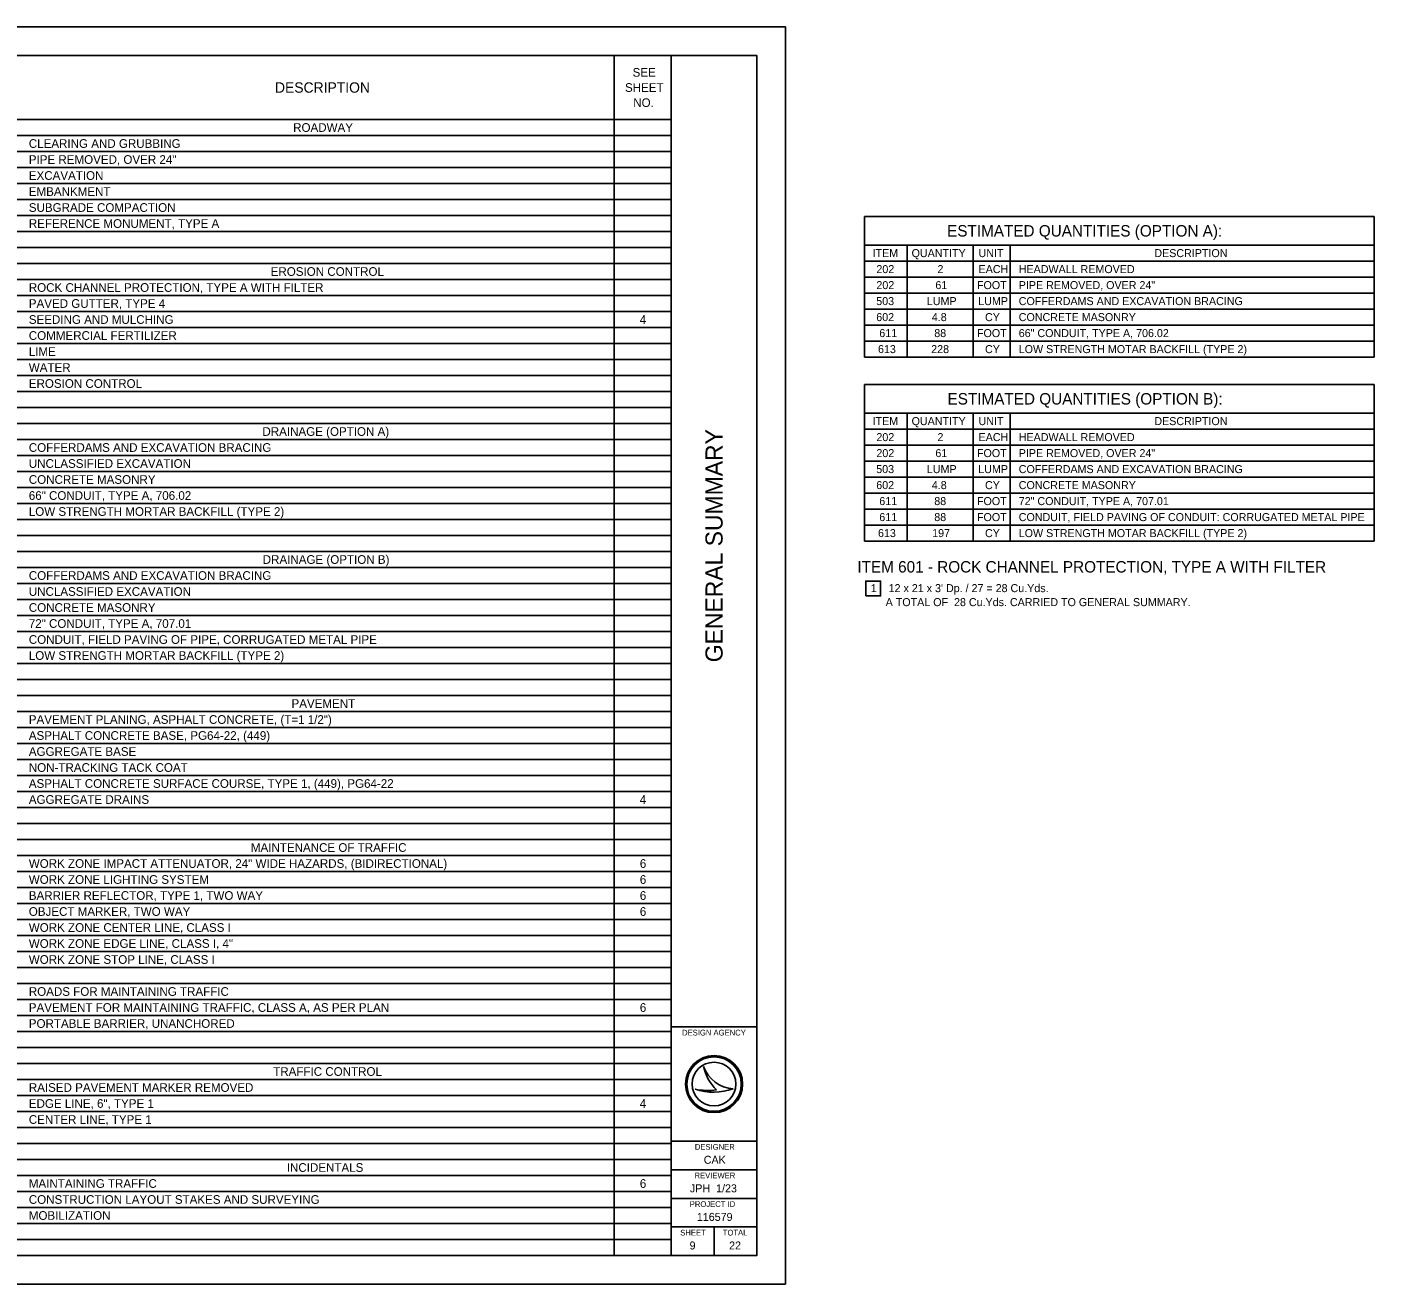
# Model space of a CAD drawing. Extents: x 0 to 44.3, y 0 to 22.
# Drawn here: x 20.73 to 44.3, y 0 to 22 of the extents above; entities that cross this region are included whole.
import ezdxf

# ---------------------------------------------------------------- set-up
doc = ezdxf.new("R2010")
doc.units = 0
for name, color, linetype in [('SH_Border', 7, 'Continuous'), ('SH_Cut_Line', 7, 'Continuous'), ('SH_Data', 7, 'Continuous'), ('SH_Text', 7, 'Continuous')]:
    doc.layers.add(name, color=color, linetype=linetype)

msp = doc.modelspace()

# ---------------------------------------------------------------- linework, layer by layer
at = {"layer": 'SH_Border'}
for p, q in [((32, 0.5), (32, 21.5)), ((32, 4.5), (33.5, 4.5)), ((32, 2.5), (33.5, 2.5)), ((32, 2), (33.5, 2)), ((32, 1.5), (33.5, 1.5)), ((32, 1), (33.5, 1))]:
    msp.add_line(p, q, dxfattribs=at)
msp.add_lwpolyline([(1.5, 21.5), (33.5, 21.5), (33.5, 0.5), (1.5, 0.5)], close=True, dxfattribs=at)
at = {"layer": 'SH_Cut_Line'}
msp.add_lwpolyline([(0, 0), (34, 0), (34, 22), (0, 22)], close=True, dxfattribs=at)
at = {"layer": 'SH_Data'}
for p, q in [((35.382, 18.682), (44.3, 18.682)), ((35.382, 16.222), (35.382, 18.682)), ((44.3, 18.682), (44.3, 16.222)), ((44.3, 18.182), (35.382, 18.182)), ((36.132, 16.222), (36.132, 18.182)), ((37.282, 16.222), (37.282, 18.182)), ((37.932, 16.222), (37.932, 18.182)), ((35.757, 18.042), (35.757, 18.042)), ((36.707, 18.042), (36.707, 18.042)), ((37.607, 18.042), (37.607, 18.042)), ((41.116, 18.042), (41.116, 18.042)), ((44.3, 17.902), (35.382, 17.902)), ((35.757, 17.762), (35.757, 17.762)), ((36.707, 17.762), (36.707, 17.762)), ((37.607, 17.762), (37.607, 17.762)), ((38.082, 17.762), (38.082, 17.762)), ((44.3, 17.622), (35.382, 17.622)), ((35.757, 17.482), (35.757, 17.482)), ((36.707, 17.482), (36.707, 17.482)), ((37.607, 17.482), (37.607, 17.482)), ((38.082, 17.482), (38.082, 17.482)), ((44.3, 17.342), (35.382, 17.342)), ((44.3, 17.062), (35.382, 17.062)), ((35.757, 17.202), (35.757, 17.202)), ((36.707, 17.202), (36.707, 17.202)), ((37.607, 17.202), (37.607, 17.202)), ((38.082, 17.202), (38.082, 17.202)), ((44.3, 16.782), (35.382, 16.782)), ((35.757, 16.922), (35.757, 16.922)), ((36.707, 16.922), (36.707, 16.922)), ((37.607, 16.922), (37.607, 16.922)), ((38.082, 16.922), (38.082, 16.922)), ((44.3, 16.502), (35.382, 16.502)), ((35.757, 16.642), (35.757, 16.642)), ((36.707, 16.642), (36.707, 16.642)), ((37.607, 16.642), (37.607, 16.642)), ((38.082, 16.642), (38.082, 16.642)), ((35.757, 16.362), (35.757, 16.362)), ((36.707, 16.362), (36.707, 16.362)), ((37.607, 16.362), (37.607, 16.362)), ((38.082, 16.362), (38.082, 16.362)), ((44.3, 16.222), (35.382, 16.222)), ((35.382, 15.742), (44.3, 15.742)), ((35.382, 13.002), (35.382, 15.742)), ((44.3, 15.742), (44.3, 13.002)), ((44.3, 15.242), (35.382, 15.242)), ((35.757, 15.102), (35.757, 15.102)), ((36.132, 13.002), (36.132, 15.242)), ((36.707, 15.102), (36.707, 15.102)), ((37.282, 13.002), (37.282, 15.242)), ((37.607, 15.102), (37.607, 15.102)), ((37.932, 13.002), (37.932, 15.242)), ((41.116, 15.102), (41.116, 15.102)), ((44.3, 14.962), (35.382, 14.962)), ((44.3, 14.682), (35.382, 14.682)), ((35.757, 14.822), (35.757, 14.822)), ((36.707, 14.822), (36.707, 14.822)), ((37.607, 14.822), (37.607, 14.822)), ((38.082, 14.822), (38.082, 14.822)), ((44.3, 14.402), (35.382, 14.402)), ((35.757, 14.542), (35.757, 14.542)), ((36.707, 14.542), (36.707, 14.542)), ((37.607, 14.542), (37.607, 14.542)), ((38.082, 14.542), (38.082, 14.542)), ((35.757, 14.262), (35.757, 14.262)), ((36.707, 14.262), (36.707, 14.262)), ((37.607, 14.262), (37.607, 14.262)), ((38.082, 14.262), (38.082, 14.262)), ((44.3, 14.122), (35.382, 14.122)), ((35.757, 13.982), (35.757, 13.982)), ((36.707, 13.982), (36.707, 13.982)), ((37.607, 13.982), (37.607, 13.982)), ((38.082, 13.982), (38.082, 13.982)), ((44.3, 13.842), (35.382, 13.842)), ((35.757, 13.702), (35.757, 13.702)), ((36.707, 13.702), (36.707, 13.702)), ((37.607, 13.702), (37.607, 13.702)), ((38.082, 13.702), (38.082, 13.702)), ((44.3, 13.562), (35.382, 13.562)), ((44.3, 13.282), (35.382, 13.282)), ((35.757, 13.422), (35.757, 13.422)), ((36.707, 13.422), (36.707, 13.422)), ((37.607, 13.422), (37.607, 13.422)), ((38.082, 13.422), (38.082, 13.422)), ((44.3, 13.002), (35.382, 13.002)), ((35.757, 13.142), (35.757, 13.142)), ((36.707, 13.142), (36.707, 13.142)), ((37.607, 13.142), (37.607, 13.142)), ((38.082, 13.142), (38.082, 13.142)), ((32.567, 3.81), (32.567, 3.81)), ((32.417, 3.41), (32.417, 3.41)), ((32.75, 3.5), (32.75, 3.5)), ((33.087, 3.419), (33.087, 3.419)), ((32.75, 0.5), (32.75, 1)), ((32.375, 0.675), (32.375, 0.675))]:
    msp.add_line(p, q, dxfattribs=at)
msp.add_lwpolyline([(35.405, 12.043), (35.665, 12.043), (35.665, 12.303), (35.405, 12.303)], close=True, dxfattribs=at)
for radius in [0.5, 0.477, 0.477, 0.382]:
    msp.add_circle((32.75, 3.5), radius, dxfattribs=at)
for centre, radius, start, end in [((33.116, 3.998), 0.58, 198.9257, 198.9319), ((33.347, 3.97), 0.796, 191.6379, 191.6421), ((33.116, 3.998), 0.58, 198.9319, 267.1657), ((33.347, 3.97), 0.796, 191.6421, 226.0947), ((32.739, 4.37), 1.013, 251.4576, 290.0832), ((32.648, 4.654), 1.266, 259.4964, 259.4995), ((32.739, 4.37), 1.013, 251.4527, 251.4576), ((32.648, 4.654), 1.266, 259.4995, 276.6672)]:
    msp.add_arc(centre, radius, start, end, dxfattribs=at)
at = {"layer": 'SH_Text'}
for p, q in [((1.5, 21.5), (32, 21.5)), ((31.002, 21.5), (31.002, 0.5)), ((32, 21.5), (32, 0.5)), ((1.5, 20.38), (32, 20.38)), ((1.5, 20.1), (32, 20.1)), ((1.5, 19.82), (32, 19.82)), ((1.5, 19.54), (32, 19.54)), ((1.5, 19.26), (32, 19.26)), ((1.5, 18.98), (32, 18.98)), ((1.5, 18.7), (32, 18.7)), ((1.5, 18.42), (32, 18.42)), ((1.5, 18.14), (32, 18.14)), ((1.5, 17.86), (32, 17.86)), ((1.5, 17.58), (32, 17.58)), ((1.5, 17.3), (32, 17.3)), ((1.5, 17.02), (32, 17.02)), ((1.5, 16.74), (32, 16.74)), ((1.5, 16.46), (32, 16.46)), ((1.5, 16.18), (32, 16.18)), ((1.5, 15.9), (32, 15.9)), ((1.5, 15.62), (32, 15.62)), ((1.5, 15.34), (32, 15.34)), ((1.5, 15.06), (32, 15.06)), ((1.5, 14.78), (32, 14.78)), ((1.5, 14.5), (32, 14.5)), ((1.5, 14.22), (32, 14.22)), ((1.5, 13.94), (32, 13.94)), ((1.5, 13.66), (32, 13.66)), ((1.5, 13.38), (32, 13.38)), ((1.5, 13.1), (32, 13.1)), ((1.5, 12.82), (32, 12.82)), ((1.5, 12.54), (32, 12.54)), ((1.5, 12.26), (32, 12.26)), ((1.5, 11.98), (32, 11.98)), ((1.5, 11.7), (32, 11.7)), ((1.5, 11.42), (32, 11.42)), ((1.5, 11.14), (32, 11.14)), ((1.5, 10.86), (32, 10.86)), ((1.5, 10.58), (32, 10.58)), ((1.5, 10.3), (32, 10.3)), ((1.5, 10.02), (32, 10.02)), ((1.5, 9.74), (32, 9.74)), ((1.5, 9.46), (32, 9.46)), ((1.5, 9.18), (32, 9.18)), ((1.5, 8.9), (32, 8.9)), ((1.5, 8.62), (32, 8.62)), ((1.5, 8.34), (32, 8.34)), ((1.5, 8.06), (32, 8.06)), ((1.5, 7.78), (32, 7.78)), ((1.5, 7.5), (32, 7.5)), ((1.5, 7.22), (32, 7.22)), ((1.5, 6.94), (32, 6.94)), ((1.5, 6.66), (32, 6.66)), ((1.5, 6.38), (32, 6.38)), ((1.5, 6.1), (32, 6.1)), ((1.5, 5.82), (32, 5.82)), ((1.5, 5.54), (32, 5.54)), ((1.5, 5.26), (32, 5.26)), ((1.5, 4.98), (32, 4.98)), ((1.5, 4.7), (32, 4.7)), ((1.5, 4.42), (32, 4.42)), ((1.5, 4.14), (32, 4.14)), ((1.5, 3.86), (32, 3.86)), ((1.5, 3.58), (32, 3.58)), ((1.5, 3.3), (32, 3.3)), ((1.5, 3.02), (32, 3.02)), ((1.5, 2.74), (32, 2.74)), ((1.5, 2.46), (32, 2.46)), ((1.5, 2.18), (32, 2.18)), ((1.5, 1.9), (32, 1.9)), ((1.5, 1.62), (32, 1.62)), ((1.5, 1.34), (32, 1.34)), ((1.5, 1.06), (32, 1.06)), ((1.5, 0.78), (32, 0.78)), ((1.5, 0.5), (32, 0.5))]:
    msp.add_line(p, q, dxfattribs=at)

# ---------------------------------------------------------------- texts
at = {"layer": 'SH_Data'}
for s, height, p in [('ESTIMATED QUANTITIES (OPTION A):', 0.2, (36.828, 18.332)), ('ITEM', 0.14, (35.524, 17.972)), ('QUANTITY', 0.14, (36.207, 17.972)), ('UNIT', 0.14, (37.379, 17.972)), ('DESCRIPTION', 0.14, (40.455, 17.972)), ('202', 0.14, (35.591, 17.692)), ('2', 0.14, (36.659, 17.692)), ('EACH', 0.14, (37.379, 17.692)), ('HEADWALL REMOVED', 0.14, (38.082, 17.692)), ('202', 0.14, (35.591, 17.412)), ('61', 0.14, (36.623, 17.412)), ('FOOT', 0.14, (37.351, 17.412)), ('PIPE REMOVED, OVER 24"', 0.14, (38.082, 17.412)), ('503', 0.14, (35.588, 17.132)), ('LUMP', 0.14, (36.474, 17.132)), ('LUMP', 0.14, (37.374, 17.132)), ('COFFERDAMS AND EXCAVATION BRACING', 0.14, (38.082, 17.132)), ('602', 0.14, (35.589, 16.852)), ('4.8', 0.14, (36.561, 16.852)), ('CY', 0.14, (37.492, 16.852)), ('CONCRETE MASONRY', 0.14, (38.082, 16.852)), ('611', 0.14, (35.642, 16.572)), ('88', 0.14, (36.604, 16.572)), ('FOOT', 0.14, (37.351, 16.572)), ('66" CONDUIT, TYPE A, 706.02', 0.14, (38.082, 16.572)), ('613', 0.14, (35.619, 16.292)), ('228', 0.14, (36.55, 16.292)), ('CY', 0.14, (37.492, 16.292)), ('LOW STRENGTH MOTAR BACKFILL (TYPE 2)', 0.14, (38.082, 16.292)), ('ESTIMATED QUANTITIES (OPTION B):', 0.2, (36.836, 15.392)), ('ITEM', 0.14, (35.524, 15.032)), ('QUANTITY', 0.14, (36.207, 15.032)), ('UNIT', 0.14, (37.379, 15.032)), ('DESCRIPTION', 0.14, (40.455, 15.032)), ('202', 0.14, (35.591, 14.752)), ('2', 0.14, (36.659, 14.752)), ('EACH', 0.14, (37.379, 14.752)), ('HEADWALL REMOVED', 0.14, (38.082, 14.752)), ('202', 0.14, (35.591, 14.472)), ('61', 0.14, (36.623, 14.472)), ('FOOT', 0.14, (37.351, 14.472)), ('PIPE REMOVED, OVER 24"', 0.14, (38.082, 14.472)), ('503', 0.14, (35.588, 14.192)), ('LUMP', 0.14, (36.474, 14.192)), ('LUMP', 0.14, (37.374, 14.192)), ('COFFERDAMS AND EXCAVATION BRACING', 0.14, (38.082, 14.192)), ('602', 0.14, (35.589, 13.912)), ('4.8', 0.14, (36.561, 13.912)), ('CY', 0.14, (37.492, 13.912)), ('CONCRETE MASONRY', 0.14, (38.082, 13.912)), ('611', 0.14, (35.642, 13.632)), ('88', 0.14, (36.604, 13.632)), ('FOOT', 0.14, (37.351, 13.632)), ('72" CONDUIT, TYPE A, 707.01', 0.14, (38.082, 13.632)), ('611', 0.14, (35.642, 13.352)), ('88', 0.14, (36.604, 13.352)), ('FOOT', 0.14, (37.351, 13.352)), ('CONDUIT, FIELD PAVING OF CONDUIT: CORRUGATED METAL PIPE', 0.14, (38.082, 13.352)), ('613', 0.14, (35.619, 13.072)), ('197', 0.14, (36.567, 13.072)), ('CY', 0.14, (37.492, 13.072)), ('LOW STRENGTH MOTAR BACKFILL (TYPE 2)', 0.14, (38.082, 13.072)), ('ITEM 601 - ROCK CHANNEL PROTECTION, TYPE A WITH FILTER', 0.2, (35.258, 12.452)), ("1    12 x 21 x 3' Dp. / 27 = 28 Cu.Yds.", 0.14, (35.493, 12.109)), ('     A TOTAL OF  28 Cu.Yds. CARRIED TO GENERAL SUMMARY. ', 0.14, (35.493, 11.864)), ('DESIGN AGENCY', 0.1, (32.191, 4.35)), ('DESIGNER', 0.1, (32.414, 2.35)), ('CAK', 0.14, (32.57, 2.105)), ('REVIEWER', 0.1, (32.409, 1.85)), ('JPH  1/23', 0.14, (32.328, 1.605)), ('PROJECT ID', 0.1, (32.325, 1.35)), ('116579', 0.14, (32.449, 1.105)), ('SHEET', 0.1, (32.158, 0.85)), ('TOTAL', 0.1, (32.903, 0.85)), ('9', 0.14, (32.322, 0.605)), ('22', 0.14, (33.013, 0.605))]:
    msp.add_text(s, height=height, dxfattribs=at).set_placement(p)
msp.add_text('GENERAL SUMMARY', height=0.3, rotation=90, dxfattribs=at).set_placement((32.9, 10.882))
at = {"layer": 'SH_Text'}
for s, height, p in [('SEE ', 0.1515, (31.325, 21.129)), ('DESCRIPTION', 0.18184, (25.067, 20.849)), ('SHEET ', 0.1515, (31.192, 20.864)), ('NO.', 0.1515, (31.336, 20.599)), ('ROADWAY', 0.1515, (25.385, 20.164)), ('CLEARING AND GRUBBING', 0.15153, (20.759, 19.884)), ('PIPE REMOVED, OVER 24"', 0.15153, (20.759, 19.604)), ('EXCAVATION', 0.1515, (20.759, 19.324)), ('EMBANKMENT', 0.1515, (20.759, 19.044)), ('SUBGRADE COMPACTION', 0.15153, (20.759, 18.764)), ('REFERENCE MONUMENT, TYPE A', 0.15153, (20.759, 18.484)), ('EROSION CONTROL', 0.15153, (24.992, 17.644)), ('ROCK CHANNEL PROTECTION, TYPE A WITH FILTER', 0.15153, (20.759, 17.364)), ('PAVED GUTTER, TYPE 4', 0.15153, (20.759, 17.084)), ('SEEDING AND MULCHING', 0.15153, (20.759, 16.804)), ('4', 0.152, (31.45, 16.804)), ('COMMERCIAL FERTILIZER', 0.15153, (20.759, 16.524)), ('LIME', 0.1515, (20.759, 16.244)), ('WATER', 0.1515, (20.759, 15.964)), ('EROSION CONTROL', 0.15153, (20.759, 15.684)), ('DRAINAGE (OPTION A)', 0.15153, (24.847, 14.844)), ('COFFERDAMS AND EXCAVATION BRACING', 0.15153, (20.759, 14.564)), ('UNCLASSIFIED EXCAVATION', 0.15153, (20.759, 14.284)), ('CONCRETE MASONRY', 0.15153, (20.759, 14.004)), ('66" CONDUIT, TYPE A, 706.02', 0.15153, (20.759, 13.724)), ('LOW STRENGTH MORTAR BACKFILL (TYPE 2)', 0.15153, (20.759, 13.444)), ('DRAINAGE (OPTION B)', 0.15153, (24.852, 12.604)), ('COFFERDAMS AND EXCAVATION BRACING', 0.15153, (20.759, 12.324)), ('UNCLASSIFIED EXCAVATION', 0.15153, (20.759, 12.044)), ('CONCRETE MASONRY', 0.15153, (20.759, 11.764)), ('72" CONDUIT, TYPE A, 707.01', 0.15153, (20.759, 11.484)), ('CONDUIT, FIELD PAVING OF PIPE, CORRUGATED METAL PIPE', 0.15153, (20.759, 11.204)), ('LOW STRENGTH MORTAR BACKFILL (TYPE 2)', 0.15153, (20.759, 10.924)), ('PAVEMENT', 0.1515, (25.356, 10.084)), ('PAVEMENT PLANING, ASPHALT CONCRETE, (T=1 1/2")', 0.15153, (20.759, 9.804)), ('ASPHALT CONCRETE BASE, PG64-22, (449)', 0.15153, (20.759, 9.524)), ('AGGREGATE BASE', 0.15153, (20.759, 9.244)), ('NON-TRACKING TACK COAT', 0.15153, (20.759, 8.964)), ('ASPHALT CONCRETE SURFACE COURSE, TYPE 1, (449), PG64-22', 0.15153, (20.759, 8.684)), ('AGGREGATE DRAINS', 0.15153, (20.759, 8.404)), ('4', 0.152, (31.45, 8.404)), ('MAINTENANCE OF TRAFFIC', 0.15153, (24.645, 7.564)), ('WORK ZONE IMPACT ATTENUATOR, 24" WIDE HAZARDS, (BIDIRECTIONAL)', 0.15153, (20.759, 7.284)), ('6', 0.152, (31.451, 7.284)), ('WORK ZONE LIGHTING SYSTEM', 0.15153, (20.759, 7.004)), ('6', 0.152, (31.451, 7.004)), ('BARRIER REFLECTOR, TYPE 1, TWO WAY', 0.15153, (20.759, 6.724)), ('6', 0.152, (31.451, 6.724)), ('OBJECT MARKER, TWO WAY', 0.15153, (20.759, 6.444)), ('6', 0.152, (31.451, 6.444)), ('WORK ZONE CENTER LINE, CLASS I', 0.15153, (20.759, 6.164)), ('WORK ZONE EDGE LINE, CLASS I, 4"', 0.15153, (20.759, 5.884)), ('WORK ZONE STOP LINE, CLASS I', 0.15153, (20.759, 5.604)), ('ROADS FOR MAINTAINING TRAFFIC', 0.15153, (20.759, 5.044)), ('PAVEMENT FOR MAINTAINING TRAFFIC, CLASS A, AS PER PLAN', 0.15153, (20.759, 4.764)), ('6', 0.152, (31.451, 4.764)), ('PORTABLE BARRIER, UNANCHORED', 0.15153, (20.759, 4.484)), ('TRAFFIC CONTROL', 0.15153, (25.036, 3.644)), ('RAISED PAVEMENT MARKER REMOVED', 0.15153, (20.759, 3.364)), ('EDGE LINE, 6", TYPE 1', 0.15153, (20.759, 3.084)), ('4', 0.152, (31.45, 3.084)), ('CENTER LINE, TYPE 1', 0.15153, (20.759, 2.804)), ('INCIDENTALS', 0.15153, (25.273, 1.964)), ('MAINTAINING TRAFFIC', 0.15153, (20.759, 1.684)), ('6', 0.152, (31.451, 1.684)), ('CONSTRUCTION LAYOUT STAKES AND SURVEYING', 0.15153, (20.759, 1.404)), ('MOBILIZATION', 0.15153, (20.759, 1.124))]:
    msp.add_text(s, height=height, dxfattribs=at).set_placement(p)

doc.saveas('drawing.dxf')
